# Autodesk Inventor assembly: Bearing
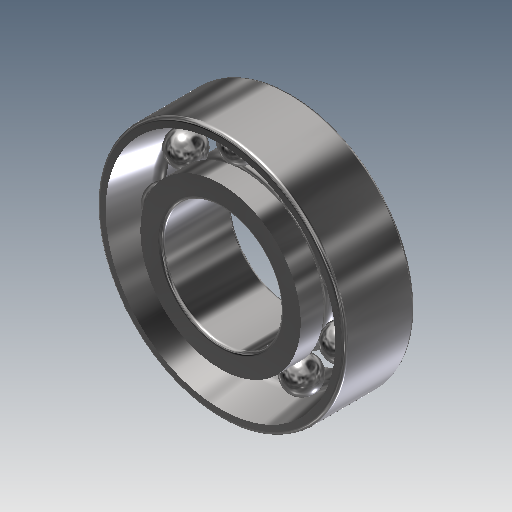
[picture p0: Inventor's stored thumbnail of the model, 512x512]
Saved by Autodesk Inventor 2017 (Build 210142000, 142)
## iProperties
Created: 2019-02
Part Number: Bearing
Document SubType Name: Assembly
Designer: user
Mass: 61.2581 g
Surface Area: 67.9445 cm^2
Volume: 7.80358 cm^3
Density: 7.85 g/cm^3
ClientObjectVersion: 1
Author: user
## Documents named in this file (2)
- C:\Users\user\Documents\EIA\Cursos\Diseño asistido por computador\Clase 7 Dynamic simulation\Ensamble reductor de velocidad\Ensamble\Design Accelerator\Bearing4.iam
- C:\Users\user\Documents\Inventor\Content Center Files\R2017\en-US\BS 292 (II)\BS 292_ Part 1 - 7004 - 20 x 42 x 12.ipt
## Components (1 placed, 1 different names)
1. BS 292: Part 1 (II) - Metric 7004 - 20 x 42 x 12:1
